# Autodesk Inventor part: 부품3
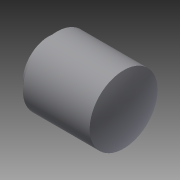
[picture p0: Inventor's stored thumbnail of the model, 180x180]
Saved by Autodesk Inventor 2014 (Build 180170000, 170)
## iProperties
Created: 2016-09
Part Number: 부품3
Material: Generic
Document SubType Name: Modeling
Designer: 702
Density: 1 g/cm^3
Appearance: Default
Author: 702
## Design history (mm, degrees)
sketch "스케치1"
  geometry: L1 (115, 0)-(5, 0); L2 (5, 0)-(5, 50); L3 (5, 50)-(103.562, 50); A1 r 115 centre (0, 0) between (115, 0) and (103.562, 50)
  constraints: 6 end point, 2 point on circle, 1 centre point, 1 horizontal, 1 parallel, 1 perpendicular
  dimensions: "d6" = 230 diameter of A1; "d7" = 110 distance of L1.start L1.end; "d8" = 50 distance of L1.end L2.end
revolve "회전1" sketch "스케치1" stored, may be unused: angle "d9" = 90 deg
sketch "스케치2"
  geometry: C1 r 50 at (0, 0) reference; C2 r 38 at (0, 0)
  constraints: 1 centre point, 1 coincident
  dimensions: "d10" = 76 diameter of C2
extrude "돌출1" join sketch "스케치2" distance "d11" = 12; taper "d12" = 0 deg
sketch "스케치3"
  geometry: C1 r 38 at (0, 0) reference; C2 r 27 at (0, 0)
  constraints: 1 centre point, 1 coincident
  dimensions: "d13" = 54 diameter of C2
extrude "돌출2" cut sketch "스케치3" distance "d14" = 15; taper "d15" = 0 deg
sketch "스케치4"
  geometry: C1 r 27 at (0, 0) reference
node "솔리드1"
